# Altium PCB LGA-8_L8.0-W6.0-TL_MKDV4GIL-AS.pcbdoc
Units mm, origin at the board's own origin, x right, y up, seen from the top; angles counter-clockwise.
Board outline 22.02 x 18.81 mm, 2 copper layers (Top Layer, Bottom Layer), stack 0 mm thick; 1 components, 0 nets, 8 pads, 0 vias.
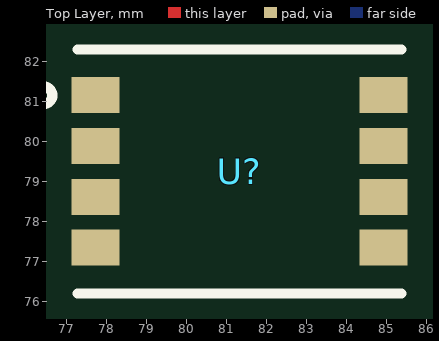
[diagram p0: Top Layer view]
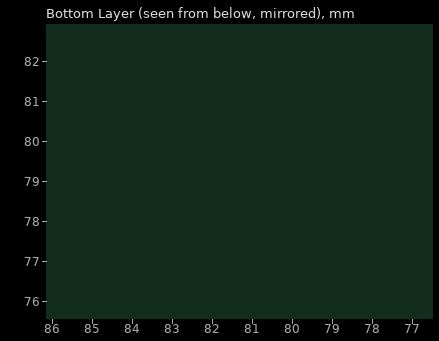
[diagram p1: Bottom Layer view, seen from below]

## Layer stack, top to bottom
Top Layer: signal copper (thickness not stored)
Bottom Layer: signal copper (thickness not stored)

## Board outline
91.873,69.85 69.85,69.85 69.85,88.66 91.873,88.66

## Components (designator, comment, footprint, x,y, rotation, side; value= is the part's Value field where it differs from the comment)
U? "" LGA-8_L8.0-W6.0-TL_MKDV4GIL-AS 81.323,79.25 r0 top

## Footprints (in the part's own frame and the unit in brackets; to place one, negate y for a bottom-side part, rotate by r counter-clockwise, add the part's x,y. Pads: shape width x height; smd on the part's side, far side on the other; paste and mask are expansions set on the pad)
LGA-8_L8.0-W6.0-TL_MKDV4GIL-AS [mm]
  rect 1.2x0.9 smd: 1(-3.6,1.905) 2(-3.6,0.635) 3(-3.6,-0.635) 4(-3.6,-1.905) 5(3.6,-1.905) 6(3.6,-0.635) 7(3.6,0.635) 8(3.6,1.905)
  silkscreen extent -5.12,-3.05 4.05,3.05

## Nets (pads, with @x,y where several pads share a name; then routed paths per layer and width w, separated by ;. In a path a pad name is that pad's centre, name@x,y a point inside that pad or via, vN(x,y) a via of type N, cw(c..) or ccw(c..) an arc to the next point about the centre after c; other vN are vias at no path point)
pads on no net: U?.1 U?.2 U?.3 U?.4 U?.5 U?.6 U?.7 U?.8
